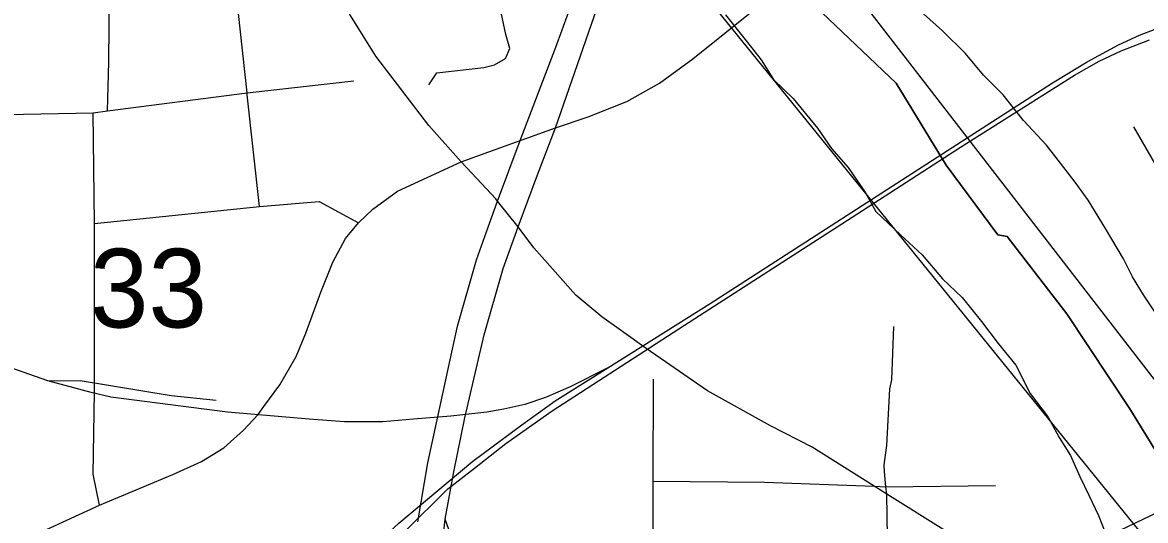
# Model space of a CAD drawing. Extents: x 0 to 34, y 0 to 22.
# Drawn here: x 5.337 to 5.934, y 17.673 to 17.938 of the extents above; entities that cross this region are included whole.
import ezdxf

# ---------------------------------------------------------------- set-up
doc = ezdxf.new("R2010")
doc.units = 0
for name, color, linetype in [('GM_X_City_Street', 7, 'Continuous'), ('GM_X_Interstate_Route', 7, 'Continuous'), ('GM_X_Major_River', 7, 'Continuous'), ('GM_X_Rail_Line', 7, 'Continuous'), ('GM_X_Section', 7, 'Continuous'), ('GM_X_Section_Text', 7, 'Continuous'), ('GM_X_State_Route', 7, 'Continuous'), ('GM_X_Township_Road', 7, 'Continuous')]:
    doc.layers.add(name, color=color, linetype=linetype)

msp = doc.modelspace()

# ---------------------------------------------------------------- linework, layer by layer
at = {"layer": 'GM_X_City_Street'}
for p, q in [((5.4626, 17.84048), (5.45615, 17.89993)), ((5.56998, 17.8643), (5.59944, 17.87486))]:
    msp.add_line(p, q, dxfattribs=at)
for points in [[(5.55264, 17.90513), (5.55693, 17.91155), (5.58192, 17.91441), (5.58763, 17.91584), (5.5935, 17.91919), (5.59588, 17.9245), (5.59366, 17.93207), (5.5862, 17.96725), (5.56986, 18.0514), (5.54683, 18.15934)], [(5.57554, 17.8583), (5.56998, 17.8643), (5.55267, 17.88359), (5.52447, 17.9205), (5.50429, 17.95312), (5.49716, 17.97514), (5.48843, 18.00718), (5.48756, 18.04312), (5.48776, 18.06524), (5.48878, 18.10634), (5.49024, 18.14618)], [(5.38183, 17.89137), (5.38249, 17.91743), (5.38313, 17.99352), (5.38377, 18.07727), (5.38257, 18.12483)], [(5.59944, 17.87486), (5.60043, 17.87521), (5.62015, 17.88228), (5.63746, 17.88812), (5.65807, 17.89636), (5.67548, 17.90615), (5.69319, 17.91901), (5.74427, 17.96017), (5.80309, 18.01104)], [(5.45615, 17.89993), (5.45604, 17.90092), (5.4454, 17.9985)], [(4.58363, 17.89219), (4.63004, 17.8916), (4.67381, 17.8916), (4.75452, 17.89122), (4.76556, 17.89113), (4.89381, 17.89047), (4.99001, 17.89113), (5.06718, 17.89019), (5.11257, 17.89073), (5.19328, 17.888), (5.2606, 17.88794), (5.29222, 17.88835), (5.31331, 17.88916), (5.32785, 17.88945), (5.37413, 17.89038), (5.38183, 17.89137), (5.45604, 17.90092), (5.51281, 17.90741)], [(5.37759, 17.68165), (5.37413, 17.69816), (5.37477, 17.74172), (5.37477, 17.83139), (5.37413, 17.89038)], [(6.02048, 17.71602), (5.9582, 17.83045), (5.92779, 17.88289)], [(5.465, 17.73405), (5.4735, 17.74562), (5.48208, 17.76078), (5.48729, 17.77308), (5.49528, 17.79502), (5.50172, 17.81084), (5.50847, 17.82342), (5.51531, 17.83183), (5.52301, 17.83917), (5.53609, 17.84857), (5.56998, 17.8643)], [(5.61297, 17.81354), (5.60856, 17.81849), (5.60032, 17.82973), (5.58927, 17.84335), (5.58834, 17.8445), (5.57554, 17.8583)], [(5.37477, 17.83139), (5.4626, 17.84048), (5.49444, 17.84313), (5.51531, 17.83183)], [(5.62936, 17.79512), (5.62397, 17.80118), (5.61297, 17.81354)], [(5.65518, 17.77438), (5.64483, 17.78184), (5.63098, 17.79331), (5.62936, 17.79512)], [(5.7972, 17.63066), (5.79631, 17.68743), (5.79591, 17.69145), (5.79512, 17.69936), (5.79499, 17.70316), (5.79633, 17.71337), (5.79797, 17.74354), (5.79898, 17.7483), (5.80005, 17.77664)], [(6.08208, 17.27609), (6.05688, 17.34121), (6.03814, 17.37854), (6.02746, 17.40002), (6.00156, 17.4483), (5.98747, 17.47328), (5.94574, 17.54472), (5.92766, 17.5738), (5.90778, 17.5981), (5.89381, 17.61452), (5.88533, 17.62262), (5.86533, 17.6417), (5.82821, 17.66755), (5.79631, 17.68743), (5.78957, 17.69168), (5.75672, 17.7124), (5.73447, 17.7239), (5.70092, 17.74247), (5.66828, 17.76493), (5.65518, 17.77438)], [(5.86533, 17.6417), (5.91576, 17.66607), (5.95387, 17.68431), (6.02048, 17.71602), (6.08562, 17.74421), (6.13447, 17.76882)], [(5.67207, 17.63353), (5.67215, 17.6944), (5.67224, 17.74863)], [(5.31382, 17.65287), (5.3361, 17.66271), (5.37759, 17.68165), (5.4166, 17.69788), (5.43172, 17.70487), (5.4437, 17.71214), (5.45406, 17.72157), (5.46196, 17.72992), (5.465, 17.73405)], [(5.67215, 17.6944), (5.73139, 17.69383), (5.78957, 17.69168), (5.79591, 17.69145), (5.85421, 17.6921)]]:
    msp.add_lwpolyline(points, dxfattribs=at)
at = {"layer": 'GM_X_Interstate_Route'}
for points in [[(5.56137, 17.67415), (5.56597, 17.69937), (5.57189, 17.7281), (5.5822, 17.77219), (5.59229, 17.8075), (5.60032, 17.82973), (5.6105, 17.85729), (5.62015, 17.88228), (5.64377, 17.95051), (5.65515, 17.97947)], [(5.54686, 17.67278), (5.55226, 17.70422), (5.56319, 17.75491), (5.56802, 17.77684), (5.57811, 17.81215), (5.58614, 17.83439), (5.58927, 17.84335), (5.60133, 17.87554), (5.62035, 17.92519), (5.6371, 17.97161)], [(5.55731, 17.61605), (5.55742, 17.618), (5.55742, 17.63424), (5.56059, 17.6662), (5.56137, 17.67415)]]:
    msp.add_lwpolyline(points, dxfattribs=at)
at = {"layer": 'GM_X_Major_River'}
for points in [[(5.94032, 17.78228), (5.93294, 17.79345), (5.92705, 17.80307), (5.9223, 17.81266), (5.91275, 17.82882), (5.90354, 17.84382), (5.89652, 17.85346), (5.88874, 17.8635), (5.88133, 17.87315), (5.86905, 17.88632), (5.8583, 17.89984), (5.84787, 17.91031), (5.83822, 17.9219), (5.82592, 17.93393), (5.81248, 17.94599)], [(5.7106, 17.94237), (5.72173, 17.92847), (5.72951, 17.91843), (5.73614, 17.90803), (5.74658, 17.89795), (5.75956, 17.8821), (5.76695, 17.87131), (5.77587, 17.86125), (5.7851, 17.84777), (5.7906, 17.83778), (5.80365, 17.82535), (5.81522, 17.81486), (5.82598, 17.8021), (5.83642, 17.79201), (5.84681, 17.77926), (5.8557, 17.76768), (5.86496, 17.75609), (5.87265, 17.74111), (5.88228, 17.72838), (5.88814, 17.71762), (5.89403, 17.708), (5.89913, 17.69688), (5.90387, 17.68691), (5.90898, 17.67616), (5.91296, 17.6662)]]:
    msp.add_lwpolyline(points, dxfattribs=at)
at = {"layer": 'GM_X_Rail_Line'}
for points in [[(5.34998, 17.74783), (5.32736, 17.75569), (5.29962, 17.76677), (5.28014, 17.7758), (5.25688, 17.78822), (5.22994, 17.80472), (5.20896, 17.81917), (5.19026, 17.83331), (5.1725, 17.84793), (5.14684, 17.87153), (5.1124, 17.90819), (5.09095, 17.93388), (5.07163, 17.95823), (5.0468, 17.99359), (5.00406, 18.0555)], [(5.18611, 17.2315), (5.30463, 17.38192), (5.4279, 17.53919), (5.4633, 17.58845), (5.4731, 17.60062), (5.4855, 17.61669), (5.50235, 17.6374), (5.51452, 17.6504), (5.52534, 17.66153), (5.53679, 17.67204), (5.57612, 17.70513), (5.60213, 17.72437), (5.62002, 17.73717), (5.6479, 17.75467), (5.7024, 17.78898), (5.77784, 17.83755), (5.8846, 17.90634), (5.90298, 17.9175), (5.91963, 17.92652), (5.93087, 17.93169), (5.94753, 17.93809)], [(5.40174, 17.22481), (5.43081, 17.35017), (5.45693, 17.46429), (5.46984, 17.52017), (5.47506, 17.54333), (5.48403, 17.57644), (5.48955, 17.59113), (5.49773, 17.60946), (5.50502, 17.62247), (5.51638, 17.64059), (5.52691, 17.65395), (5.53964, 17.66731), (5.56276, 17.69031), (5.57704, 17.7014), (5.59369, 17.71444), (5.61836, 17.73189), (5.68876, 17.7773), (5.77802, 17.83482), (5.83567, 17.87212), (5.89621, 17.91035), (5.90933, 17.91785), (5.92099, 17.92338), (5.93606, 17.92909)], [(5.6479, 17.75467), (5.62795, 17.74461), (5.61475, 17.73896), (5.60383, 17.73511), (5.59259, 17.73275), (5.58364, 17.7311), (5.56447, 17.72898), (5.54459, 17.72733), (5.52825, 17.72599), (5.50782, 17.72599), (5.48904, 17.72741), (5.44561, 17.73116), (5.38353, 17.73904), (5.37308, 17.74163), (5.34998, 17.74783)], [(5.34998, 17.74783), (5.3672, 17.74802), (5.41566, 17.74005), (5.43966, 17.73757)]]:
    msp.add_lwpolyline(points, dxfattribs=at)
at = {"layer": 'GM_X_Section'}
for points in [[(5.03965, 18.48463), (5.61791, 18.48139), (5.53096, 18.32812), (5.55642, 18.12958), (5.94095, 17.65517), (5.94104, 17.65505), (5.94524, 17.63735), (5.96217, 17.59121), (6.02854, 17.45475), (6.02664, 17.37374), (5.04609, 17.39252)], [(5.65796, 18.11177), (6.11806, 18.06871), (6.07317, 17.51262), (6.01213, 17.65383)]]:
    msp.add_lwpolyline(points, close=True, dxfattribs=at)
at = {"layer": 'GM_X_State_Route'}
for points in [[(5.56137, 17.67415), (5.56597, 17.69937), (5.57189, 17.7281), (5.5822, 17.77219), (5.59229, 17.8075), (5.60032, 17.82973), (5.6105, 17.85729), (5.62015, 17.88228), (5.64377, 17.95051), (5.65515, 17.97947)], [(5.56422, 17.66625), (5.56137, 17.67415)]]:
    msp.add_lwpolyline(points, dxfattribs=at)
at = {"layer": 'GM_X_Township_Road'}
for points in [[(5.94883, 17.69515), (5.92567, 17.73288), (5.89222, 17.78348), (5.86048, 17.82463), (5.85546, 17.82552), (5.828, 17.8624), (5.80142, 17.90613), (5.74404, 17.9607)], [(5.74404, 17.9607), (5.80142, 17.90613), (5.828, 17.8624), (5.85546, 17.82552), (5.86048, 17.82463), (5.89222, 17.78348), (5.92567, 17.73288), (5.94883, 17.69515)]]:
    msp.add_lwpolyline(points, dxfattribs=at)

# ---------------------------------------------------------------- texts
at = {"layer": 'GM_X_Section_Text'}
msp.add_text('33', height=0.041856, rotation=0.00001, dxfattribs=at).set_placement((5.37243, 17.77616))

doc.saveas('drawing.dxf')
